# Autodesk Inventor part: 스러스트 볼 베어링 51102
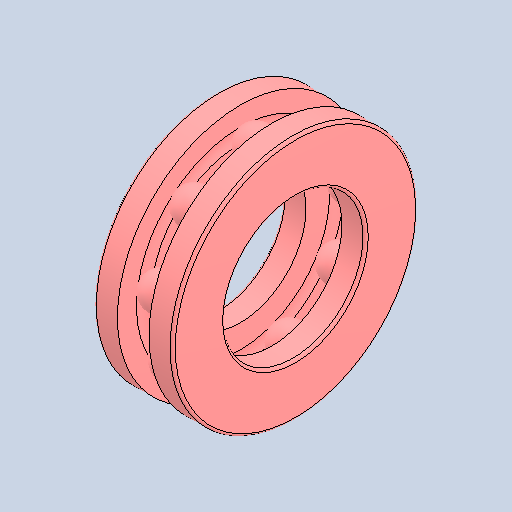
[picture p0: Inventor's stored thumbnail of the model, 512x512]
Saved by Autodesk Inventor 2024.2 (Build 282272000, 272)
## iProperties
Created: 2025-09
Part Number: 스러스트 볼 베어링 51102
Material: 강철, 연강
Description: 롤링 베어링 - 플랫 뒷면이 있는 스러스트 볼 베어링
Document SubType Name: Modeling
Designer: home
Density: 7.85 g/cm^3
Appearance: 기본값
Author: jhkim
Sending System: Autodesk Inventor 2026
Preprocessor: ST-DEVELOPER v20.1
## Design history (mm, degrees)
feature "Solid1"
feature "Solid1:1"
feature "Solid1:2"
feature "Solid1:3"
feature "Solid1:4"
feature "Solid1:5"
feature "Solid1:6"
feature "Solid1:7"
feature "Solid1:8"
feature "Solid1:9"
feature "Solid1:10"
node "솔리드1"
node "솔리드2"
node "솔리드3"
node "솔리드4"
node "솔리드5"
node "솔리드6"
node "솔리드7"
node "솔리드8"
node "솔리드9"
node "솔리드10"
node "솔리드11"
